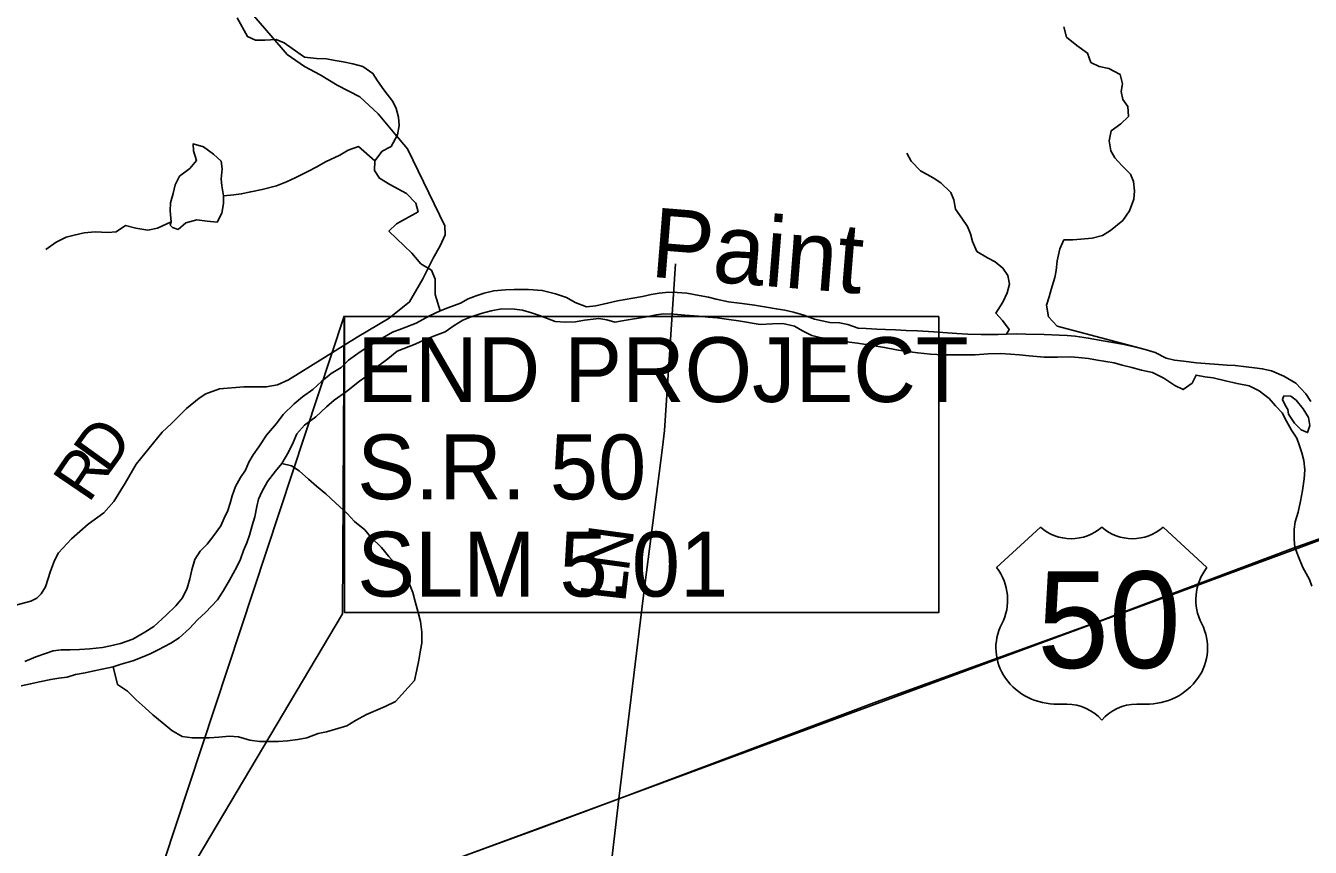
# Model space of a CAD drawing. Extents: x -139 to 835, y 0 to 440.
# Drawn here: x 494.5 to 550, y 308.2 to 343.7 of the extents above; entities that cross this region are included whole.
import ezdxf

# ---------------------------------------------------------------- set-up
doc = ezdxf.new("R2010")
doc.units = 0
for name, color, linetype in [('GM_X_Major_River', 7, 'Continuous'), ('GM_X_Major_River_Text', 7, 'Continuous'), ('GM_X_Minor_Lake', 7, 'Continuous'), ('GM_X_Minor_River', 7, 'Continuous'), ('GM_X_Rail_Line', 7, 'Continuous'), ('GM_X_Township_Road', 7, 'Continuous'), ('GM_X_Township_Road_Text', 7, 'Continuous'), ('GM_X_US_Location', 7, 'Continuous'), ('GM_X_US_Route', 7, 'Continuous'), ('GM_X_US_Shield', 7, 'Continuous'), ('SH_Text', 7, 'Continuous')]:
    doc.layers.add(name, color=color, linetype=linetype)

msp = doc.modelspace()

# ---------------------------------------------------------------- linework, layer by layer
at = {"layer": 'GM_X_Major_River'}
for points in [[(542.91, 329.735), (542.521, 329.835), (541.936, 329.961), (541.52, 330.038), (541.091, 330.114), (540.454, 330.229), (539.881, 330.307), (539.543, 330.335), (539.191, 330.351), (538.54, 330.382), (537.758, 330.391), (537.341, 330.407), (536.924, 330.4), (536.559, 330.38), (535.829, 330.376), (535.243, 330.394), (534.774, 330.423), (534.162, 330.466), (533.785, 330.494), (533.069, 330.537), (532.587, 330.555), (532.131, 330.584), (531.688, 330.6), (531.323, 330.616), (530.855, 330.645), (530.516, 330.661), (530.062, 330.81), (529.711, 330.886), (529.294, 330.902), (528.618, 331.042), (528.164, 331.215), (527.723, 331.351), (527.346, 331.427), (526.969, 331.491), (526.553, 331.556), (526.032, 331.646), (525.499, 331.723), (524.914, 331.79), (524.381, 331.903), (524.043, 331.991), (523.64, 332.067), (523.107, 332.169), (522.69, 332.198), (522.326, 332.202), (521.921, 332.17), (521.568, 332.102), (521.189, 332.022), (520.771, 331.943), (520.118, 331.83), (519.687, 331.727), (519.177, 331.624), (518.773, 331.568), (518.28, 331.766), (517.905, 331.974), (517.438, 332.135), (516.866, 332.285), (516.267, 332.328), (515.655, 332.322), (515.277, 332.314), (514.768, 332.272), (514.35, 332.168), (514.009, 332.052), (513.656, 331.924), (513.328, 331.736), (512.778, 331.538), (512.45, 331.409), (511.991, 331.186), (511.414, 330.869), (510.781, 330.625)], [(549.382, 321.195), (549.347, 321.531), (549.34, 321.975), (549.396, 322.298), (549.519, 322.705), (549.616, 323.184), (549.7, 323.651), (549.785, 324.142), (549.803, 324.537), (549.769, 324.945), (549.682, 325.27), (549.581, 325.571), (549.455, 325.897), (549.238, 326.247), (549.022, 326.633), (548.831, 326.995), (548.535, 327.298), (548.265, 327.613), (547.84, 327.954), (547.399, 328.162), (546.879, 328.264), (546.385, 328.377), (545.853, 328.503), (545.489, 328.555), (545.112, 328.631), (544.938, 328.273), (544.556, 328.001), (544.194, 328.185), (543.716, 328.502), (543.223, 328.736), (542.755, 328.837), (542.327, 328.961), (541.911, 329.062), (541.574, 329.161), (541.21, 329.213), (540.845, 329.277), (540.455, 329.342), (540.026, 329.394), (539.687, 329.41), (539.127, 329.404), (538.54, 329.398), (537.902, 329.453), (537.486, 329.506), (537.096, 329.534), (536.64, 329.563), (536.131, 329.544), (535.57, 329.503), (535.036, 329.508), (534.189, 329.506), (533.642, 329.535), (533.095, 329.589), (532.523, 329.668), (532.172, 329.719), (531.652, 329.821), (531.197, 329.886), (530.846, 329.95), (530.481, 330.002), (530.143, 330.053), (529.688, 330.13), (529.272, 330.195), (528.855, 330.247), (528.505, 330.335), (528.103, 330.543), (527.754, 330.739), (527.26, 330.852), (526.817, 330.845), (526.282, 330.815), (525.346, 330.969), (524.917, 331.034), (524.423, 331.099), (524.032, 331.127), (523.628, 331.168), (523.017, 331.222), (522.548, 331.264), (522.105, 331.268), (521.779, 331.224), (521.361, 331.145), (520.407, 330.987), (520.002, 330.919), (519.652, 331.007), (519.301, 331.071), (518.687, 330.994), (518.295, 330.926), (517.865, 330.907), (517.422, 330.935), (516.748, 331.207), (516.398, 331.318), (516.008, 331.431), (515.67, 331.47), (515.097, 331.488), (514.653, 331.409), (514.221, 331.294), (513.789, 331.143), (513.435, 331.003), (513.055, 330.767), (512.673, 330.495), (512.215, 330.32), (511.769, 330.145), (511.376, 329.969), (510.598, 329.655)], [(510.781, 330.625), (510.388, 330.486), (509.953, 330.226), (509.4, 329.884), (508.992, 329.637), (508.49, 329.27), (508.173, 328.962), (507.751, 328.702), (507.328, 328.347), (506.945, 328.003), (506.51, 327.696), (506.14, 327.388), (505.676, 326.925), (505.384, 326.532), (504.946, 326.033), (504.625, 325.532), (504.373, 325.187), (504.185, 324.865), (504.05, 324.518), (503.824, 324.209), (503.609, 323.815), (503.473, 323.409), (503.377, 323.098), (503.281, 322.775), (503.12, 322.452), (502.972, 322.118), (502.679, 321.701), (502.386, 321.332), (502.082, 321.024), (501.855, 320.666), (501.731, 320.223), (501.634, 319.828), (501.524, 319.433), (501.323, 319.004), (501.03, 318.659), (500.62, 318.267), (500.078, 317.769), (499.696, 317.533), (499.169, 317.227), (498.644, 317.041), (498.212, 316.937), (497.872, 316.869), (497.322, 316.803), (496.865, 316.784), (496.473, 316.764), (496.081, 316.769), (495.728, 316.725), (495.4, 316.608), (494.98, 316.457), (494.507, 316.258)], [(510.598, 329.655), (510.189, 329.336), (509.74, 329.005), (509.304, 328.601), (508.974, 328.365), (508.406, 327.915), (507.879, 327.549), (507.548, 327.252), (507.085, 326.825), (506.597, 326.471), (506.265, 326.09), (506.104, 325.72), (505.902, 325.302), (505.608, 324.813), (505.342, 324.48), (504.996, 324.028), (504.755, 323.587), (504.607, 323.276), (504.537, 322.953), (504.44, 322.51), (504.33, 322.127), (504.22, 321.72), (504.098, 321.385), (503.963, 321.051), (503.827, 320.68), (503.666, 320.346), (503.357, 319.773), (503.09, 319.32), (502.836, 318.927), (502.319, 318.381), (501.975, 318.06), (501.618, 317.692), (501.181, 317.289), (500.812, 317.053), (500.273, 316.771), (499.931, 316.595), (499.577, 316.454), (499.183, 316.291), (498.671, 316.152), (498.33, 316.036), (497.846, 315.933), (497.439, 315.842), (497.112, 315.773), (496.706, 315.694), (496.339, 315.59), (495.973, 315.534), (495.633, 315.49), (495.148, 315.387), (494.755, 315.295), (494.349, 315.204)], [(550.062, 327.486), (549.858, 327.812), (549.421, 328.284), (548.903, 328.578), (548.372, 328.812), (547.969, 328.9), (547.631, 328.94), (547.28, 328.991), (546.798, 329.045), (546.446, 329.06), (546.082, 329.088), (545.496, 329.131), (545.131, 329.159), (544.559, 329.225), (544.182, 329.277), (543.818, 329.353), (543.339, 329.598), (542.91, 329.735)], [(549.104, 326.944), (549.359, 326.546), (549.655, 326.266), (549.928, 326.144), (550.023, 326.454), (549.962, 326.803), (549.732, 327.177), (549.437, 327.54), (549.205, 327.723), (548.905, 327.726), (548.838, 327.571), (548.978, 327.305), (549.067, 327.149)], [(549.067, 327.149), (549.104, 326.944)], [(550.103, 319.507), (550.003, 319.808), (549.722, 320.315), (549.533, 320.773), (549.382, 321.195)]]:
    msp.add_lwpolyline(points, dxfattribs=at)
at = {"layer": 'GM_X_Minor_Lake'}
for points in [[(501.139, 334.919), (501.469, 335.204), (501.941, 335.331), (502.384, 335.278), (502.814, 335.237), (503.016, 335.619), (503.087, 336.038), (503.091, 336.374), (503.019, 336.807), (502.997, 337.107), (503.029, 337.527), (502.994, 337.863), (502.659, 338.167), (502.233, 338.484), (501.777, 338.609), (501.799, 338.309), (501.924, 337.899), (501.632, 337.542), (501.196, 337.211), (501.008, 336.841), (500.912, 336.47), (500.802, 336.063), (500.784, 335.727), (500.83, 335.247)], [(500.83, 335.247), (500.792, 335.105), (500.885, 335.003), (501.139, 334.919)]]:
    msp.add_lwpolyline(points, dxfattribs=at)
at = {"layer": 'GM_X_Minor_River'}
for points in [[(503.68, 344.061), (504.127, 343.252), (504.477, 343.092), (504.882, 343.087), (505.366, 343.118), (505.716, 342.982), (506.065, 342.726), (506.596, 342.361), (507.117, 342.295), (507.548, 342.278), (507.912, 342.214), (508.264, 342.15), (508.681, 342.074), (509.11, 341.949), (509.55, 341.656), (509.741, 341.33), (510.023, 340.943), (510.408, 340.446), (510.548, 340.145), (510.66, 339.76), (510.681, 339.411), (510.61, 339.004), (510.329, 338.503), (509.948, 338.303), (509.628, 337.875), (509.609, 337.455), (509.827, 337.128), (510.28, 336.86), (511.003, 336.464)], [(542.91, 329.735), (539.105, 330.736), (538.732, 331.148), (538.647, 331.641), (538.756, 332.011), (538.852, 332.322), (539.001, 332.836), (539.058, 333.148), (539.115, 333.567), (539.226, 334.082), (539.4, 334.464), (539.778, 334.471), (540.13, 334.492), (540.613, 334.534), (541.071, 334.661), (541.412, 334.874), (541.939, 335.3), (542.231, 335.717), (542.42, 336.218), (542.451, 336.59), (542.404, 336.986), (542.278, 337.3), (541.905, 337.676), (541.596, 338.015), (541.431, 338.317), (541.358, 338.749), (541.442, 339.18), (541.863, 339.476), (542.192, 339.796), (542.159, 340.228), (541.941, 340.53), (541.88, 340.879), (541.937, 341.202), (541.825, 341.611), (541.333, 341.869), (540.917, 341.957), (540.567, 342.129), (540.416, 342.526), (539.964, 342.855), (539.513, 343.22), (539.401, 343.665)], [(509.628, 337.875), (508.919, 338.495), (508.473, 338.344), (508.117, 338.131), (507.499, 337.838), (507.13, 337.614), (506.736, 337.426), (506.184, 337.144), (505.816, 336.968), (505.382, 336.793), (504.767, 336.644), (504.269, 336.541), (503.863, 336.45), (503.536, 336.405), (503.091, 336.374)], [(536.924, 330.4), (537.031, 330.602), (536.749, 330.989), (536.454, 331.304), (536.76, 331.781), (536.947, 332.175), (537.056, 332.558), (536.983, 332.93), (536.765, 333.245), (536.43, 333.524), (536.093, 333.696), (535.641, 333.965), (535.451, 334.399), (535.364, 334.723), (535.237, 335.037), (534.994, 335.399), (534.713, 335.786), (534.64, 336.195), (534.513, 336.508), (534.089, 336.933), (533.753, 337.14), (533.209, 337.446), (532.798, 337.87), (532.62, 338.208)], [(511.003, 336.464), (511.402, 336.051), (511.502, 335.678), (510.57, 335.152)], [(500.83, 335.247), (500.238, 334.965), (499.819, 334.886), (499.311, 334.975), (498.856, 335.088), (498.46, 334.817), (498.094, 334.785), (497.546, 334.815), (497.075, 334.772), (496.643, 334.669), (496.289, 334.577), (495.868, 334.365), (495.42, 334.058)], [(510.57, 335.152), (510.239, 334.844), (511.231, 333.894)], [(511.231, 333.894), (511.616, 333.434), (512.082, 333.153), (512.233, 332.767), (512.242, 332.443), (512.238, 332.107), (512.45, 331.409)], [(505.608, 324.813), (506.024, 324.713), (506.361, 324.493), (506.761, 324.129), (507.109, 323.837), (507.509, 323.496), (507.935, 323.108), (508.438, 322.658), (508.746, 322.307), (509.198, 321.942), (509.455, 321.627), (509.919, 321.178), (510.24, 320.79), (510.884, 320.065)], [(510.884, 320.065), (511.101, 319.667), (511.278, 319.245), (511.377, 318.848), (511.501, 318.379), (511.6, 317.982), (511.66, 317.526), (511.654, 317.058), (511.597, 316.746), (511.527, 316.315), (511.443, 315.896), (511.346, 315.441), (510.519, 314.534)], [(498.33, 316.036), (498.515, 315.266), (498.942, 314.973), (499.316, 314.609), (499.703, 314.257), (500.038, 313.953), (500.438, 313.625), (500.864, 313.284), (501.305, 313.015), (501.735, 312.962), (502.087, 312.959), (502.479, 312.966), (502.885, 312.998), (503.342, 313.041), (503.747, 313.012), (504.228, 312.863), (504.645, 312.811), (505.128, 312.805), (505.468, 312.813), (505.86, 312.833), (506.304, 312.888), (506.697, 312.968), (507.183, 313.155), (507.536, 313.223), (508.035, 313.361), (508.428, 313.489), (508.797, 313.713), (509.27, 313.972), (509.678, 314.148), (510.072, 314.323), (510.519, 314.534)]]:
    msp.add_lwpolyline(points, dxfattribs=at)
at = {"layer": 'GM_X_Rail_Line'}
msp.add_lwpolyline([(461.72, 306.518), (463.204, 305.984), (481.829, 301.388), (483.589, 301.041), (485.626, 300.734), (487.707, 300.627), (489.642, 300.667), (491.519, 300.827), (493.891, 301.254), (496.306, 301.869), (510.606, 306.801), (564.86, 326.817)], dxfattribs=at)
at = {"layer": 'GM_X_Township_Road'}
for points in [[(492.909, 318.383), (494.765, 318.869), (495.03, 318.995), (495.218, 319.183), (495.41, 319.491), (495.624, 320.158), (495.794, 320.622), (495.96, 320.955), (496.526, 321.554), (497.249, 322.186), (497.916, 322.675), (498.348, 323.169), (498.841, 323.962), (499.321, 324.779), (500.444, 326.158), (500.846, 326.533), (501.142, 326.838), (501.492, 327.178), (502.04, 327.634), (502.333, 327.819), (502.914, 328.034), (503.975, 328.118), (504.941, 328.12), (505.427, 328.206), (505.904, 328.423), (508.869, 330.264), (510.251, 331.085), (511.133, 331.785), (511.697, 332.78), (512.153, 333.67), (512.455, 334.203), (512.664, 334.679), (512.649, 335.075), (511.043, 338.4), (510.5, 339.048), (509.779, 339.904), (508.976, 340.643), (507.997, 341.145), (507.265, 341.593), (506.596, 341.956), (505.839, 342.478), (505.143, 343.285), (504.396, 344.142)], [(522.053, 325.507), (522.145, 326.237), (522.625, 333.431)], [(520.178, 310.331), (521.229, 319.002), (522.053, 325.507)], [(515.847, 296.553), (517.823, 296.547), (518.16, 296.621), (518.309, 296.819), (518.476, 297.476), (518.664, 298.264), (518.905, 300.443), (519.182, 301.788), (520.178, 310.331)]]:
    msp.add_lwpolyline(points, dxfattribs=at)
at = {"layer": 'GM_X_US_Route'}
msp.add_lwpolyline([(497.834, 302.1), (498.811, 302.471), (508.647, 305.997), (512.08, 307.344), (516.823, 309.075), (520.178, 310.331), (531.308, 314.514), (540.741, 317.927), (549.297, 321.159), (555.655, 323.421)], dxfattribs=at)
at = {"layer": 'GM_X_US_Shield'}
for p, q in [((538.383, 322.06), (536.49, 320.323)), ((545.577, 320.323), (543.684, 322.06)), ((539.141, 314.418), (539.519, 314.418)), ((542.548, 314.418), (542.927, 314.418))]:
    msp.add_line(p, q, dxfattribs=at)
for centre, major_axis, start_param, end_param in [((539.709, 323.3), (1.893, 0), 3.936991, 5.487786), ((542.359, 323.3), (1.893, 0), 3.936991, 5.487786), ((534.319, 318.928), (2.65, 0), 5.838949, 6.894067), ((547.749, 318.928), (-2.65, 0), 5.672304, 6.727422), ((539.111, 316.849), (2.65, 0), 2.702327, 4.723529), ((542.957, 316.849), (2.65, 0), 4.701249, 6.722451), ((539.519, 312.681), (-1.893, 0), 3.785094, 4.712389), ((542.548, 312.681), (-1.893, 0), 4.712389, 5.639684)]:
    msp.add_ellipse(centre, major_axis=major_axis, ratio=0.917426, start_param=start_param, end_param=end_param, dxfattribs=at)
at = {"layer": 'SH_Text'}
for points in [[(498.811, 302.471), (508.23, 318.313), (508.3, 331.165)], [(508.326, 331.157), (533.991, 331.157), (533.991, 318.375), (508.326, 318.375)]]:
    msp.add_lwpolyline(points, close=True, dxfattribs=at)

# ---------------------------------------------------------------- texts
at = {"layer": 'GM_X_Major_River_Text'}
msp.add_text('Paint', height=3.003, rotation=355.4088, dxfattribs=at).set_placement((521.491, 332.876))
at = {"layer": 'GM_X_Township_Road_Text'}
for s, height, rotation, p in [('D', 1.985, 54.3087, (498.112, 324.3)), ('R', 1.985, 55.8663, (497.27, 323.058)), ('N', 1.961, 82.1891, (520.592, 320.09)), ('L', 1.96, 83.6447, (520.444, 318.764))]:
    msp.add_text(s, height=height, rotation=rotation, dxfattribs=at).set_placement(p)
at = {"layer": 'GM_X_US_Location'}
for s, p in [('/', (541.032, 318.032)), ('0', (541.031, 318.032))]:
    msp.add_text(s, height=0.00599, dxfattribs=at).set_placement(p)
msp.add_text('50', height=0.00599, rotation=0, dxfattribs=at).set_placement((539.684, 316.793))
at = {"layer": 'GM_X_US_Shield'}
msp.add_text('50', height=4.1684, dxfattribs=at).set_placement((538.246, 315.981))
at = {"layer": 'SH_Text'}
for s, p in [('END PROJECT', (508.869, 327.464)), ('S.R. 50            ', (508.869, 323.264)), ('SLM 5.01        ', (508.869, 319.064))]:
    msp.add_text(s, height=2.79999, dxfattribs=at).set_placement(p)

doc.saveas('drawing.dxf')
